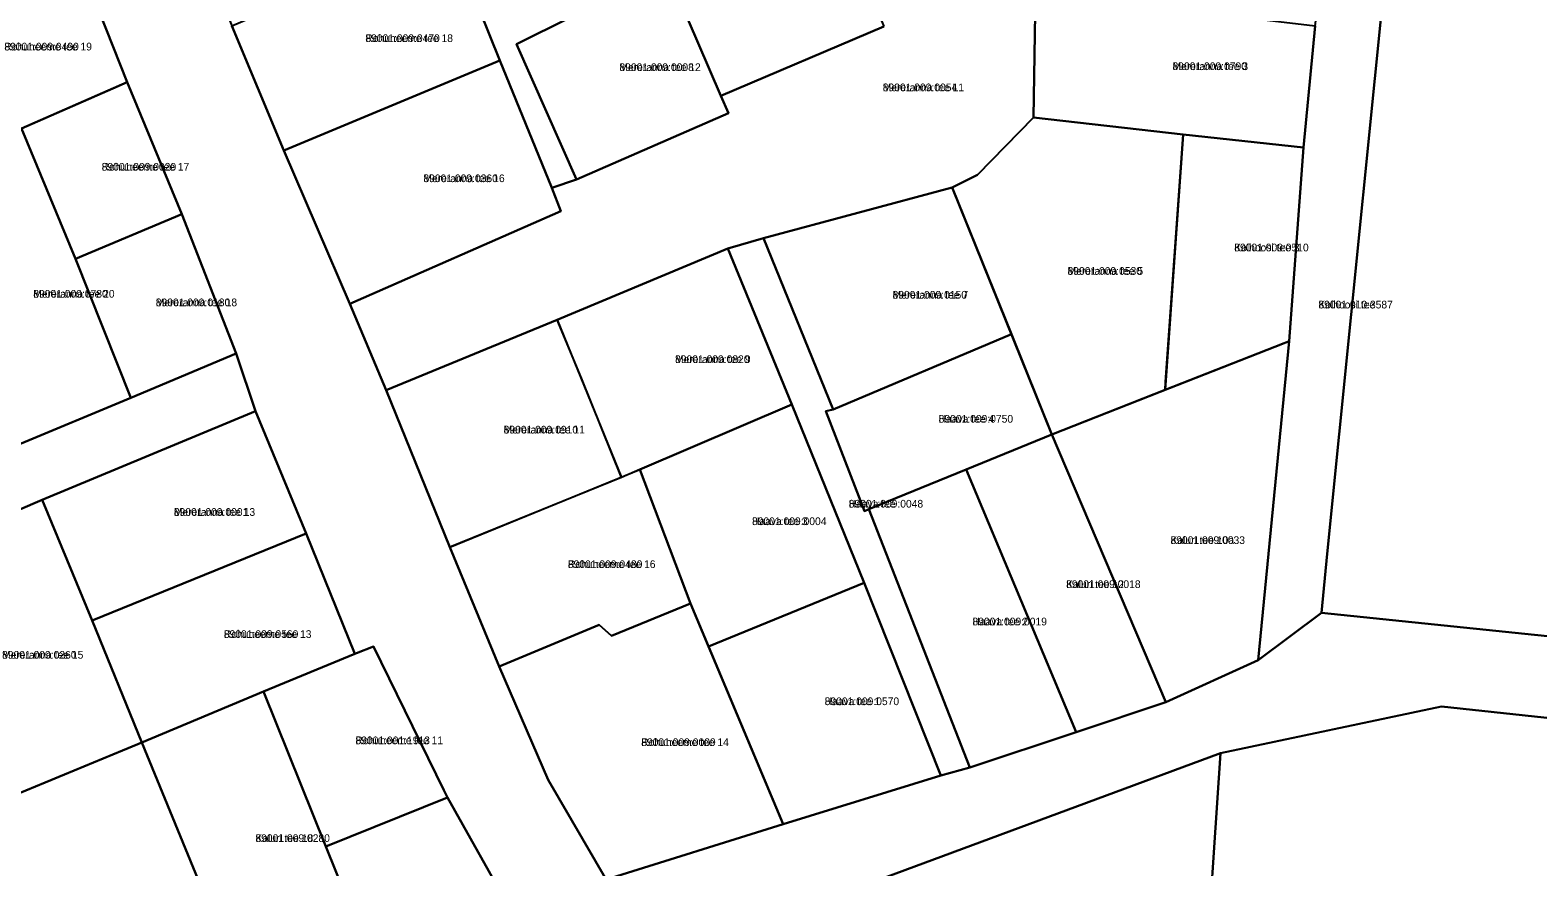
# Model space of a CAD drawing. Extents: x 526849 to 562296, y 6591741 to 6618546.
# Drawn here: x 546425 to 546718.7, y 6597216.4 to 6597379.4 of the extents above; entities that cross this region are included whole.
import ezdxf

# ---------------------------------------------------------------- set-up
doc = ezdxf.new("R2010")
doc.units = 0
for name, color, linetype in [('L_AADRESS', 7, 'Continuous'), ('PIIR', 7, 'Continuous'), ('TUNNUS', 7, 'Continuous')]:
    doc.layers.add(name, color=color, linetype=linetype)

msp = doc.modelspace()

# ---------------------------------------------------------------- linework, layer by layer
at = {"layer": 'PIIR'}
for points in [[(546518.84, 6597207.6), (546506.3, 6597229.96), (546505.57, 6597231.38), (546491.92, 6597259.35), (546488.56, 6597258.05), (546488.29, 6597257.91), (546478.8, 6597281.4), (546468.93, 6597305.22), (546465.16, 6597316.47), (546454.55, 6597343.58), (546443.93, 6597369.28), (546432.91, 6597397.19), (546421.29, 6597426.81), (546411.93, 6597436.48), (546410.43, 6597440), (546399.32, 6597466.03), (546388.52, 6597493.4), (546369.58, 6597537.93), (546367.53, 6597546.74), (546351.26, 6597587.7), (546333.49, 6597635.23), (546325.71, 6597651.46), (546311.88, 6597687.95)], [(546342.66, 6597681.78), (546354.23, 6597657.41), (546357.46, 6597649.31), (546392.86, 6597560.66), (546412.75, 6597510.84), (546426.07, 6597477.61), (546439.94, 6597443.89), (546443.57, 6597434.34), (546442.75, 6597434.03), (546454.27, 6597405.68), (546464.29, 6597380.24), (546474.4, 6597355.96), (546487.3, 6597326.14), (546494.39, 6597309.27), (546506.79, 6597278.69), (546516.4, 6597255.45), (546525.91, 6597233.41), (546537.23, 6597214.01)], [(546620.82, 6597386.73), (546620.44, 6597362.42), (546609.51, 6597351.25), (546604.57, 6597348.75), (546567.86, 6597338.88), (546560.88, 6597336.9), (546527.65, 6597323.03), (546494.39, 6597309.27), (546487.3, 6597326.14), (546528.4, 6597344.16), (546526.63, 6597348.68), (546531.46, 6597350.36), (546561.03, 6597363.25), (546559.57, 6597366.65), (546591.27, 6597380.16)], [(546537.23, 6597214.01), (546571.67, 6597224.76), (546602.37, 6597234.23), (546608.02, 6597235.83), (546628.75, 6597242.71), (546646.25, 6597248.51), (546664.23, 6597256.73), (546676.52, 6597265.96), (546784.04, 6597254.84), (546792.2, 6597253.99), (546903.67, 6597242.46), (546984.63, 6597234.82), (546997.07, 6597233.51), (546996.5, 6597228.14), (547009.65, 6597226.75), (547010.23, 6597232.12), (547061.13, 6597226.75), (547138.2, 6597218.62), (547158.27, 6597216.51), (547151.38, 6597199.62)], [(547143.53, 6597200.45), (546969.6, 6597217.47), (546938.63, 6597220.5), (546938.88, 6597222.99), (546822.49, 6597234.51), (546699.94, 6597247.66), (546656.88, 6597238.58), (546552.45, 6597199.91)]]:
    msp.add_lwpolyline(points, dxfattribs=at)
for points in [[(546676.52, 6597265.96), (546664.23, 6597256.73), (546670.26, 6597318.87), (546673, 6597356.56), (546675.3, 6597380.29), (546676.43, 6597388.53), (546678.65, 6597413.6), (546678.92, 6597425.79), (546681.44, 6597454.12), (546652.81, 6597456.17), (546650.66, 6597461.24), (546682.43, 6597459.2), (546686.08, 6597495.66), (546689.19, 6597526.6), (546701.21, 6597525.66), (546693.63, 6597433.12), (546692.94, 6597425.43), (546691.61, 6597416.72), (546677.67, 6597277.42)], [(546496.86, 6597421.68), (546527.23, 6597433.11), (546534.74, 6597415.12), (546544.61, 6597391.02), (546529.14, 6597384.45), (546530.31, 6597381.93), (546519.74, 6597376.71), (546531.46, 6597350.36), (546526.63, 6597348.68), (546516.48, 6597373.5), (546506.57, 6597398.26)], [(546692.94, 6597425.43), (546702.76, 6597424.7), (546797.47, 6597417.44), (546799.87, 6597418.32), (546803.01, 6597418.21), (546792.67, 6597336.4), (546784.04, 6597254.84), (546676.52, 6597265.96), (546677.67, 6597277.42), (546691.61, 6597416.72)], [(546591.27, 6597380.16), (546559.57, 6597366.65), (546550.92, 6597386.77), (546582.9, 6597400.7)], [(546406.65, 6597353.75), (546395.83, 6597382.55), (546432.91, 6597397.19), (546443.93, 6597369.28), (546423.36, 6597360.27)], [(546464.29, 6597380.24), (546506.57, 6597398.26), (546516.48, 6597373.5), (546474.4, 6597355.96)], [(546544.61, 6597391.02), (546548.43, 6597392.55), (546550.92, 6597386.77), (546559.57, 6597366.65), (546561.03, 6597363.25), (546531.46, 6597350.36), (546519.74, 6597376.71), (546530.31, 6597381.93), (546529.14, 6597384.45)], [(546620.82, 6597386.73), (546675.3, 6597380.29), (546673, 6597356.56), (546649.58, 6597359.12), (546620.44, 6597362.42)], [(546528.4, 6597344.16), (546487.3, 6597326.14), (546474.4, 6597355.96), (546516.48, 6597373.5), (546526.63, 6597348.68)], [(546423.36, 6597360.27), (546442.19, 6597368.52), (546443.93, 6597369.28), (546454.55, 6597343.58), (546433.83, 6597334.85)], [(546609.51, 6597351.25), (546620.44, 6597362.42), (546649.58, 6597359.12), (546646.08, 6597309.35), (546624.01, 6597300.67), (546604.57, 6597348.75)], [(546422.49, 6597298.59), (546410.06, 6597328.51), (546416.52, 6597331.2), (546406.65, 6597353.75), (546423.36, 6597360.27), (546433.83, 6597334.85), (546444.62, 6597307.78)], [(546649.58, 6597359.12), (546673, 6597356.56), (546670.26, 6597318.87), (546669.26, 6597318.46), (546646.08, 6597309.35), (546646.18, 6597310.86)], [(546604.57, 6597348.75), (546616.16, 6597320.23), (546581.4, 6597305.51), (546567.86, 6597338.88)], [(546454.55, 6597343.58), (546465.16, 6597316.47), (546444.62, 6597307.78), (546433.83, 6597334.85)], [(546602.37, 6597234.23), (546587.45, 6597271.79), (546573.38, 6597306.53), (546560.88, 6597336.9), (546567.86, 6597338.88), (546581.4, 6597305.51), (546580, 6597305.18), (546587.52, 6597285.71), (546588.37, 6597286.12), (546608.02, 6597235.83)], [(546560.88, 6597336.9), (546573.38, 6597306.53), (546543.8, 6597293.86), (546540.17, 6597292.27), (546532.41, 6597311.66), (546527.65, 6597323.03)], [(546506.79, 6597278.69), (546494.39, 6597309.27), (546527.65, 6597323.03), (546540.17, 6597292.27)], [(546616.16, 6597320.23), (546624.01, 6597300.67), (546607.34, 6597293.87), (546588.37, 6597286.12), (546587.52, 6597285.71), (546580, 6597305.18), (546581.4, 6597305.51)], [(546624.01, 6597300.67), (546645.09, 6597308.96), (546669.26, 6597318.46), (546670.26, 6597318.87), (546664.23, 6597256.73), (546646.25, 6597248.51)], [(546465.16, 6597316.47), (546468.93, 6597305.22), (546427.34, 6597287.94), (546392.32, 6597272.86), (546384.9, 6597270.64), (546362.53, 6597261.42), (546335.77, 6597250.06), (546311.71, 6597240.22), (546280.16, 6597226.98), (546252.62, 6597215.62), (546251.54, 6597228.33), (546275.37, 6597238.16), (546306.72, 6597251.2), (546314.93, 6597254.74), (546322.07, 6597257.76), (546351.26, 6597269.6), (546364.33, 6597274.71), (546381.26, 6597281.71), (546388.65, 6597284.14), (546422.49, 6597298.59), (546444.62, 6597307.78)], [(546557.17, 6597259.36), (546553.66, 6597267.75), (546543.8, 6597293.86), (546573.38, 6597306.53), (546587.45, 6597271.79)], [(546468.93, 6597305.22), (546478.8, 6597281.4), (546437.1, 6597264.42), (546427.34, 6597287.94)], [(546607.34, 6597293.87), (546624.01, 6597300.67), (546646.25, 6597248.51), (546628.75, 6597242.71)], [(546553.66, 6597267.75), (546538.24, 6597261.46), (546535.84, 6597263.58), (546516.4, 6597255.45), (546506.79, 6597278.69), (546543.8, 6597293.86)], [(546588.37, 6597286.12), (546607.34, 6597293.87), (546628.75, 6597242.71), (546608.02, 6597235.83)], [(546412.79, 6597226.62), (546411.78, 6597227.74), (546392.32, 6597272.86), (546427.34, 6597287.94), (546437.1, 6597264.42), (546446.77, 6597240.69)], [(546437.1, 6597264.42), (546478.8, 6597281.4), (546488.29, 6597257.91), (546470.47, 6597250.61), (546446.77, 6597240.69)], [(546571.67, 6597224.76), (546557.17, 6597259.36), (546587.45, 6597271.79), (546602.37, 6597234.23)], [(546571.67, 6597224.76), (546537.23, 6597214.01), (546525.91, 6597233.41), (546516.4, 6597255.45), (546535.84, 6597263.58), (546538.24, 6597261.46), (546553.66, 6597267.75)], [(546482.62, 6597220.39), (546470.47, 6597250.61), (546488.29, 6597257.91), (546488.56, 6597258.05), (546491.92, 6597259.35), (546505.57, 6597231.38), (546506.3, 6597229.96)], [(546446.77, 6597240.69), (546470.47, 6597250.61), (546482.62, 6597220.39), (546491.03, 6597199.44), (546466.78, 6597191.98)], [(546656.88, 6597238.58), (546699.94, 6597247.66), (546822.49, 6597234.51), (546817.04, 6597170.88), (546813.62, 6597138.11), (546811.54, 6597118.4), (546822.09, 6597105.44), (546971.66, 6597090.28), (546965.68, 6597032.55), (546961.11, 6597033.02), (546955.13, 6596973.03), (546923.5, 6596975.57), (546904.28, 6596977.11), (546808.63, 6596984.86), (546804.34, 6596942.6), (546801.58, 6596915.51), (546796.45, 6596865.11), (546779.92, 6596848.46), (546751.14, 6596851.26), (546773.35, 6597081.3), (546739.97, 6597085.37), (546743.83, 6597123.65), (546650.29, 6597132.9), (546650.53, 6597143.8)], [(546446.77, 6597240.69), (546466.78, 6597191.98), (546431.99, 6597181.07), (546412.79, 6597226.62)], [(546656.88, 6597238.58), (546650.53, 6597143.8), (546640.1, 6597144.19), (546581.56, 6597145.98), (546552.45, 6597199.91)], [(546491.03, 6597199.44), (546482.62, 6597220.39), (546506.3, 6597229.96), (546518.84, 6597207.6), (546510.07, 6597205.36)]]:
    msp.add_lwpolyline(points, close=True, dxfattribs=at)

# ---------------------------------------------------------------- texts
at = {"layer": 'L_AADRESS'}
for s, p in [('Rohuneeme tee 18', (546490.31, 6597377.11)), ('Rohuneeme tee 19', (546419.99, 6597375.47)), ('Mereranna tee 12', (546539.79, 6597371.46)), ('Mereranna tee 3', (546647.52, 6597371.65)), ('Mereranna tee L1', (546591.08, 6597367.53)), ('Rohuneeme tee 17', (546438.95, 6597352.06)), ('Mereranna tee 16', (546501.61, 6597349.82)), ('Kolhoosi tee 3', (546659.54, 6597336.34)), ('Mereranna tee 5', (546627.07, 6597331.77)), ('Mereranna tee 20', (546425.63, 6597327.32)), ('Mereranna tee 18', (546449.49, 6597325.65)), ('Mereranna tee 7', (546592.99, 6597327.13)), ('Kolhoosi tee', (546675.93, 6597325.22)), ('Mereranna tee 9', (546550.63, 6597314.58)), ('Mereranna tee 11', (546517.24, 6597300.86)), ('Haava tee 4', (546601.97, 6597302.97)), ('Haava tee', (546584.45, 6597286.43)), ('Mereranna tee 13', (546453.01, 6597284.82)), ('Haava tee 3', (546565.62, 6597283.02)), ('Kaluri tee 10a', (546647.13, 6597279.34)), ('Rohuneeme tee 16', (546529.76, 6597274.65)), ('Kaluri tee 12', (546626.8, 6597270.76)), ('Haava tee 2', (546608.56, 6597263.48)), ('Rohuneeme tee 13', (546462.75, 6597261.04)), ('Mereranna tee 15', (546419.55, 6597257)), ('Haava tee 1', (546579.77, 6597247.95)), ('Rohuneeme tee 11', (546488.38, 6597240.34)), ('Rohuneeme tee 14', (546544.04, 6597239.98)), ('Kaluri tee 18', (546468.9, 6597221.29))]:
    msp.add_text(s, height=1.5, dxfattribs=at).set_placement(p)
at = {"layer": 'TUNNUS'}
for s, p in [('89001:009:0490', (546419.99, 6597375.47)), ('89001:009:0470', (546490.31, 6597377.11)), ('89001:009:0008', (546539.79, 6597371.46)), ('89001:009:0790', (546647.52, 6597371.65)), ('89001:009:0054', (546591.08, 6597367.53)), ('89001:009:0020', (546438.95, 6597352.06)), ('89001:009:0360', (546501.61, 6597349.82)), ('89001:009:0510', (546659.54, 6597336.34)), ('89001:009:0530', (546627.07, 6597331.77)), ('89001:009:0780', (546425.63, 6597327.32)), ('89001:009:0180', (546449.49, 6597325.65)), ('89001:009:0150', (546592.99, 6597327.13)), ('89001:010:3587', (546675.93, 6597325.22)), ('89001:009:0820', (546550.63, 6597314.58)), ('89001:009:0910', (546517.24, 6597300.86)), ('89001:009:0750', (546601.97, 6597302.97)), ('89001:009:0048', (546584.45, 6597286.43)), ('89001:009:0001', (546453.01, 6597284.82)), ('89001:009:0004', (546565.62, 6597283.02)), ('89001:009:0033', (546647.13, 6597279.34)), ('89001:009:0480', (546529.76, 6597274.65)), ('89001:009:0018', (546626.8, 6597270.76)), ('89001:009:0019', (546608.56, 6597263.48)), ('89001:009:0560', (546462.75, 6597261.04)), ('89001:009:0260', (546419.55, 6597257)), ('89001:009:0570', (546579.77, 6597247.95)), ('89001:001:1913', (546488.38, 6597240.34)), ('89001:009:0009', (546544.04, 6597239.98)), ('89001:009:0280', (546468.9, 6597221.29))]:
    msp.add_text(s, height=1.5, dxfattribs=at).set_placement(p)

doc.saveas('drawing.dxf')
